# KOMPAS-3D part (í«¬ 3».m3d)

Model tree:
1. Эскиз:1
2. Операция выдавливания:1
     Расстояние 1 = 3
3. Эскиз:2
4. Операция выдавливания:2
     Расстояние 1 = 78
5. Эскиз:3
6. Операция выдавливания:3
     Расстояние 1 = 3
7. Эскиз:4
8. Операция выдавливания:4
     Расстояние 1 = 4
9. Эскиз:5
10. Операция выдавливания:5
     Расстояние 1 = 4
11. Эскиз:6
12. Вырезать элемент выдавливания:1
     Расстояние 2 = 110; Расстояние 1 = 100
